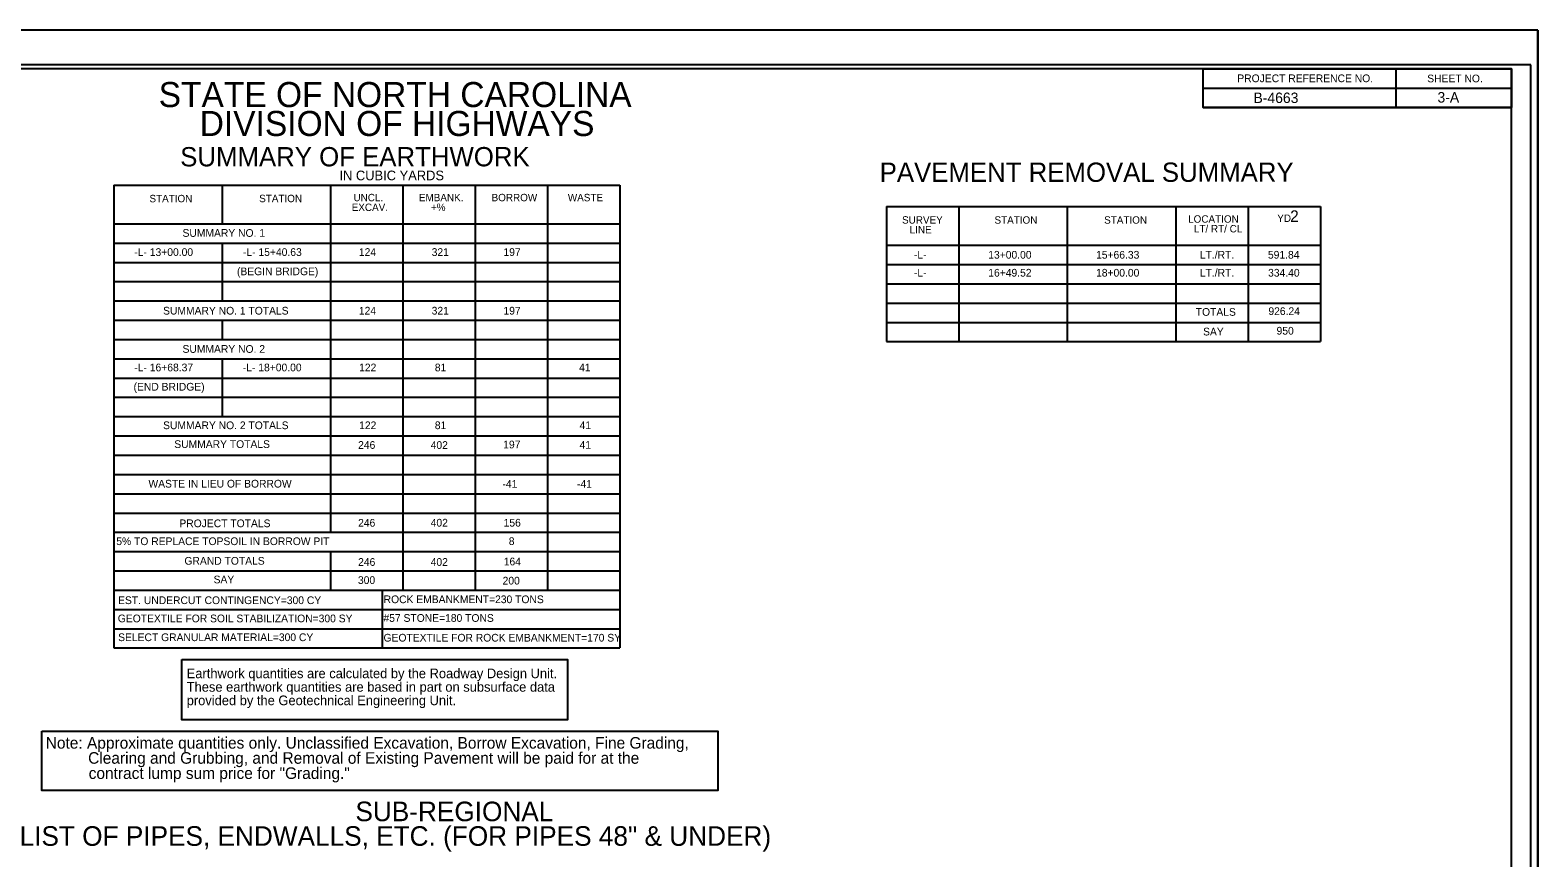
# Model space of a CAD drawing. Extents: x 573852.2 to 573885.9, y -53312.9 to -53240.3.
# Drawn here: x 573866.32 to 573885.87, y -53301.6 to -53290.86 of the extents above; entities that cross this region are included whole.
import ezdxf

# ---------------------------------------------------------------- set-up
doc = ezdxf.new("R2010")
doc.units = 0
for name, color, linetype in [('Prop DSN Text', 7, 'Continuous'), ('Prop Grid Mask', 7, 'Continuous'), ('Prop XSC Text', 7, 'Continuous'), ('Sheet Cutting Line CELL', 7, 'Continuous'), ('Sheet Data Field CELL', 7, 'Continuous'), ('Sheet Pipe Summary CELL', 7, 'Continuous'), ('Sheet Plot Border Inside CELL', 7, 'Continuous'), ('Sheet Plot Border Outside CELL', 7, 'Continuous'), ('Sheet Summary Combination CELL', 7, 'Continuous'), ('Sheet Summary Combination Grid CELL', 7, 'Continuous'), ('Sheet Summary Earthwork CELL', 7, 'Continuous')]:
    doc.layers.add(name, color=color, linetype=linetype)

msp = doc.modelspace()

# ---------------------------------------------------------------- linework, layer by layer
at = {"layer": 'Prop Grid Mask'}
msp.add_lwpolyline([(573866.47, -53299.955), (573875.237, -53299.955), (573875.237, -53300.724), (573866.47, -53300.724)], close=True, dxfattribs=at)
at = {"layer": 'Sheet Cutting Line CELL'}
for q in [(573852.191, -53290.865), (573885.871, -53312.865)]:
    msp.add_line((573885.871, -53290.865), q, dxfattribs=at)
at = {"layer": 'Sheet Plot Border Inside CELL'}
msp.add_lwpolyline([(573885.781, -53291.314), (573852.451, -53291.314), (573852.451, -53312.416), (573885.781, -53312.416)], close=True, dxfattribs=at)
at = {"layer": 'Sheet Plot Border Outside CELL'}
msp.add_lwpolyline([(573885.871, -53290.865), (573852.191, -53290.865), (573852.191, -53312.865), (573885.871, -53312.865)], close=True, dxfattribs=at)
at = {"layer": 'Sheet Summary Combination CELL'}
for p, q in [((573884.031, -53291.366), (573884.031, -53291.866)), ((573881.53, -53291.616), (573885.531, -53291.616)), ((573881.53, -53291.866), (573885.531, -53291.866)), ((573869.29, -53292.876), (573869.29, -53292.876)), ((573869.415, -53292.878), (573869.415, -53292.878)), ((573869.596, -53292.874), (573869.596, -53292.874)), ((573869.708, -53292.876), (573869.708, -53292.876)), ((573880.249, -53293.154), (573880.249, -53293.154)), ((573880.374, -53293.156), (573880.374, -53293.156)), ((573880.555, -53293.152), (573880.555, -53293.152)), ((573880.667, -53293.154), (573880.667, -53293.154))]:
    msp.add_line(p, q, dxfattribs=at)
msp.add_lwpolyline([(573885.531, -53312.365), (573885.531, -53291.365), (573855.531, -53291.365), (573855.531, -53312.365)], dxfattribs=at)
msp.add_lwpolyline([(573881.53, -53291.365), (573885.531, -53291.365), (573885.531, -53291.866), (573881.53, -53291.866)], close=True, dxfattribs=at)
at = {"layer": 'Sheet Summary Combination Grid CELL'}
for p, q in [((573867.403, -53292.875), (573873.968, -53292.875)), ((573867.403, -53292.875), (573867.403, -53298.875)), ((573868.81, -53292.875), (573868.81, -53293.375)), ((573870.216, -53292.875), (573870.216, -53297.375)), ((573871.154, -53292.875), (573871.154, -53298.125)), ((573872.092, -53292.875), (573872.092, -53298.125)), ((573873.03, -53292.875), (573873.03, -53298.125)), ((573873.968, -53292.875), (573873.968, -53298.875)), ((573877.424, -53293.153), (573883.051, -53293.153)), ((573877.424, -53293.153), (573877.424, -53294.903)), ((573878.362, -53293.153), (573878.362, -53294.903)), ((573879.769, -53293.153), (573879.769, -53294.903)), ((573881.175, -53293.153), (573881.175, -53294.903)), ((573882.113, -53293.153), (573882.113, -53294.903)), ((573883.051, -53293.153), (573883.051, -53294.903)), ((573867.403, -53293.375), (573873.968, -53293.375)), ((573867.403, -53293.625), (573873.968, -53293.625)), ((573868.81, -53293.625), (573868.81, -53294.375)), ((573877.424, -53293.653), (573883.051, -53293.653)), ((573867.403, -53293.875), (573873.968, -53293.875)), ((573877.424, -53293.903), (573883.051, -53293.903)), ((573867.403, -53294.125), (573873.968, -53294.125)), ((573877.424, -53294.153), (573883.051, -53294.153)), ((573867.403, -53294.375), (573873.968, -53294.375)), ((573867.403, -53294.375), (573873.968, -53294.375)), ((573877.424, -53294.403), (573883.051, -53294.403)), ((573867.403, -53294.625), (573873.968, -53294.625)), ((573868.81, -53294.625), (573868.81, -53294.875)), ((573877.424, -53294.653), (573883.051, -53294.653)), ((573867.403, -53294.875), (573873.968, -53294.875)), ((573877.424, -53294.903), (573883.051, -53294.903)), ((573877.424, -53294.903), (573883.051, -53294.903)), ((573867.403, -53295.125), (573873.968, -53295.125)), ((573868.81, -53295.125), (573868.81, -53295.875)), ((573867.403, -53295.375), (573873.968, -53295.375)), ((573867.403, -53295.375), (573873.968, -53295.375)), ((573867.403, -53295.625), (573873.968, -53295.625)), ((573867.403, -53295.875), (573873.968, -53295.875)), ((573867.403, -53295.875), (573873.968, -53295.875)), ((573867.403, -53296.125), (573873.968, -53296.125)), ((573867.403, -53296.125), (573873.968, -53296.125)), ((573867.403, -53296.375), (573873.968, -53296.375)), ((573867.403, -53296.625), (573873.968, -53296.625)), ((573867.403, -53296.875), (573873.968, -53296.875)), ((573867.403, -53297.125), (573873.968, -53297.125)), ((573867.403, -53297.125), (573873.968, -53297.125)), ((573867.403, -53297.375), (573873.968, -53297.375)), ((573867.403, -53297.625), (573873.968, -53297.625)), ((573867.403, -53297.625), (573873.968, -53297.625)), ((573870.216, -53297.625), (573870.216, -53298.125)), ((573867.403, -53297.875), (573873.968, -53297.875)), ((573867.403, -53298.125), (573873.968, -53298.125)), ((573870.882, -53298.125), (573870.882, -53298.875)), ((573867.403, -53298.375), (573873.968, -53298.375)), ((573867.403, -53298.625), (573873.968, -53298.625)), ((573867.403, -53298.875), (573873.968, -53298.875))]:
    msp.add_line(p, q, dxfattribs=at)
at = {"layer": 'Sheet Summary Earthwork CELL'}
msp.add_lwpolyline([(573868.286, -53299.025), (573873.287, -53299.025), (573873.287, -53299.805), (573868.286, -53299.805)], close=True, dxfattribs=at)

# ---------------------------------------------------------------- texts
at = {"layer": 'Prop DSN Text'}
for s, p in [('SUMMARY NO. 1', (573868.295, -53293.544)), ('-L- 13+00.00', (573867.67, -53293.792)), ('-L- 15+40.63', (573869.079, -53293.792)), ('124', (573870.582, -53293.792)), ('321', (573871.526, -53293.792)), ('197', (573872.457, -53293.792)), ('-L- ', (573877.78, -53293.827)), ('13+00.00', (573878.744, -53293.827)), ('15+66.33', (573880.142, -53293.827)), ('LT./RT.', (573881.488, -53293.827)), ('591.84', (573882.371, -53293.827)), ('(BEGIN BRIDGE)', (573869.001, -53294.042)), ('-L- ', (573877.78, -53294.06)), ('16+49.52', (573878.744, -53294.06)), ('18+00.00', (573880.142, -53294.06)), ('LT./RT.', (573881.488, -53294.06)), ('334.40', (573882.373, -53294.06)), ('SUMMARY NO. 1 TOTALS', (573868.043, -53294.552)), ('124', (573870.582, -53294.552)), ('321', (573871.526, -53294.552)), ('197', (573872.457, -53294.552)), ('TOTALS', (573881.435, -53294.568)), ('926.24', (573882.377, -53294.558)), ('950', (573882.483, -53294.812)), ('SAY', (573881.53, -53294.823)), ('SUMMARY NO. 2', (573868.295, -53295.048)), ('-L- 16+68.37', (573867.67, -53295.288)), ('-L- 18+00.00', (573869.077, -53295.288)), ('122', (573870.585, -53295.288)), ('81', (573871.567, -53295.288)), ('41', (573873.438, -53295.288)), ('(END BRIDGE)', (573867.66, -53295.538)), ('SUMMARY NO. 2 TOTALS', (573868.043, -53296.038)), ('122', (573870.585, -53296.038)), ('81', (573871.567, -53296.038)), ('41', (573873.444, -53296.038)), ('SUMMARY TOTALS', (573868.188, -53296.282)), ('246', (573870.572, -53296.293)), ('402', (573871.513, -53296.294)), ('197', (573872.454, -53296.287)), ('41', (573873.444, -53296.292)), ('WASTE IN LIEU OF BORROW', (573867.853, -53296.795)), ('-41', (573872.444, -53296.798)), ('-41', (573873.411, -53296.798)), ('PROJECT TOTALS', (573868.254, -53297.309)), ('246', (573870.572, -53297.302)), ('402', (573871.513, -53297.301)), ('156', (573872.459, -53297.301)), ('5% TO REPLACE TOPSOIL IN BORROW PIT', (573867.436, -53297.541)), ('8', (573872.526, -53297.54)), ('GRAND TOTALS', (573868.32, -53297.795)), ('246', (573870.572, -53297.81)), ('402', (573871.513, -53297.81)), ('164', (573872.461, -53297.804)), ('SAY', (573868.698, -53298.037)), ('300', (573870.57, -53298.045)), ('200', (573872.446, -53298.052)), ('EST. UNDERCUT CONTINGENCY=300 CY', (573867.459, -53298.306)), ('ROCK EMBANKMENT=230 TONS', (573870.903, -53298.294)), ('GEOTEXTILE FOR SOIL STABILIZATION=300 SY', (573867.456, -53298.542)), ('#57 STONE=180 TONS', (573870.901, -53298.536)), ('SELECT GRANULAR MATERIAL=300 CY', (573867.46, -53298.786)), ('GEOTEXTILE FOR ROCK EMBANKMENT=170 SY', (573870.902, -53298.792))]:
    msp.add_text(s, height=0.1, dxfattribs=at).set_placement(p)
at = {"layer": 'Prop XSC Text'}
for s, p in [('Note: Approximate quantities only. Unclassified Excavation, Borrow Excavation, Fine Grading, ', (573866.521, -53300.18)), ('Clearing and Grubbing, and Removal of Existing Pavement will be paid for at the  ', (573867.071, -53300.376)), ('contract lump sum price for "Grading."', (573867.078, -53300.573))]:
    msp.add_text(s, height=0.15, dxfattribs=at).set_placement(p)
at = {"layer": 'Sheet Data Field CELL'}
for s, p in [('B-4663   ', (573882.184, -53291.809)), ('3-A', (573884.57, -53291.803))]:
    msp.add_text(s, height=0.135, dxfattribs=at).set_placement(p)
at = {"layer": 'Sheet Pipe Summary CELL'}
for s, p in [('SUB-REGIONAL', (573870.537, -53301.121)), ('LIST OF PIPES, ENDWALLS, ETC. (FOR PIPES 48" & UNDER)', (573866.182, -53301.44))]:
    msp.add_text(s, height=0.254, dxfattribs=at).set_placement(p)
at = {"layer": 'Sheet Summary Combination CELL'}
for s, height, p in [('STATE OF NORTH CAROLINA', 0.325, (573867.986, -53291.862)), ('PROJECT REFERENCE NO.', 0.1, (573881.974, -53291.539)), ('SHEET NO.', 0.1, (573884.437, -53291.541)), ('DIVISION OF HIGHWAYS', 0.325, (573868.518, -53292.237)), ('STATION', 0.096, (573867.866, -53293.096)), ('STATION', 0.096, (573869.289, -53293.095)), ('EXCAV.', 0.096, (573870.489, -53293.209)), ('UNCL.', 0.096, (573870.512, -53293.083)), ('EMBANK.', 0.096, (573871.36, -53293.083)), ('+%', 0.096, (573871.517, -53293.209)), ('BORROW', 0.096, (573872.303, -53293.083)), ('WASTE', 0.096, (573873.292, -53293.083)), ('SURVEY', 0.096, (573877.626, -53293.373)), ('STATION', 0.096, (573878.825, -53293.374)), ('STATION', 0.096, (573880.247, -53293.374)), ('LOCATION', 0.096, (573881.336, -53293.361)), ('LINE', 0.096, (573877.725, -53293.499)), ('LT/ RT/ CL', 0.096, (573881.411, -53293.487))]:
    msp.add_text(s, height=height, dxfattribs=at).set_placement(p)
for s, height, p in [('SUMMARY OF EARTHWORK', 0.25, (573868.265, -53292.631)), ('IN CUBIC YARDS', 0.125, (573870.33, -53292.811)), ('PAVEMENT REMOVAL SUMMARY', 0.25, (573877.336, -53292.832))]:
    msp.add_text(s, height=height, rotation=0.0119, dxfattribs=at).set_placement(p)
at = {"layer": 'Sheet Summary Combination Grid CELL'}
for s, height, p in [('YD', 0.096, (573882.492, -53293.351)), ('2', 0.15, (573882.659, -53293.351))]:
    msp.add_text(s, height=height, dxfattribs=at).set_placement(p)
at = {"layer": 'Sheet Summary Earthwork CELL'}
for s, p in [('Earthwork quantities are calculated by the Roadway Design Unit. ', (573868.349, -53299.267)), ('These earthwork quantities are based in part on subsurface data ', (573868.349, -53299.442)), ('provided by the Geotechnical Engineering Unit.', (573868.349, -53299.617))]:
    msp.add_text(s, height=0.125, dxfattribs=at).set_placement(p)

doc.saveas('drawing.dxf')
